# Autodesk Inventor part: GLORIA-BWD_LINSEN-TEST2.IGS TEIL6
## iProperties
Created: 2005-04
Part Number: GLORIA-BWD_LINSEN-TEST2.IGS TEIL6
Document SubType Name: Modeling
Designer: Nordmeyer
Manufacturer: Standard
Standards Organization: Custom
Author: Nordmeyer
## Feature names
1. Erst1
